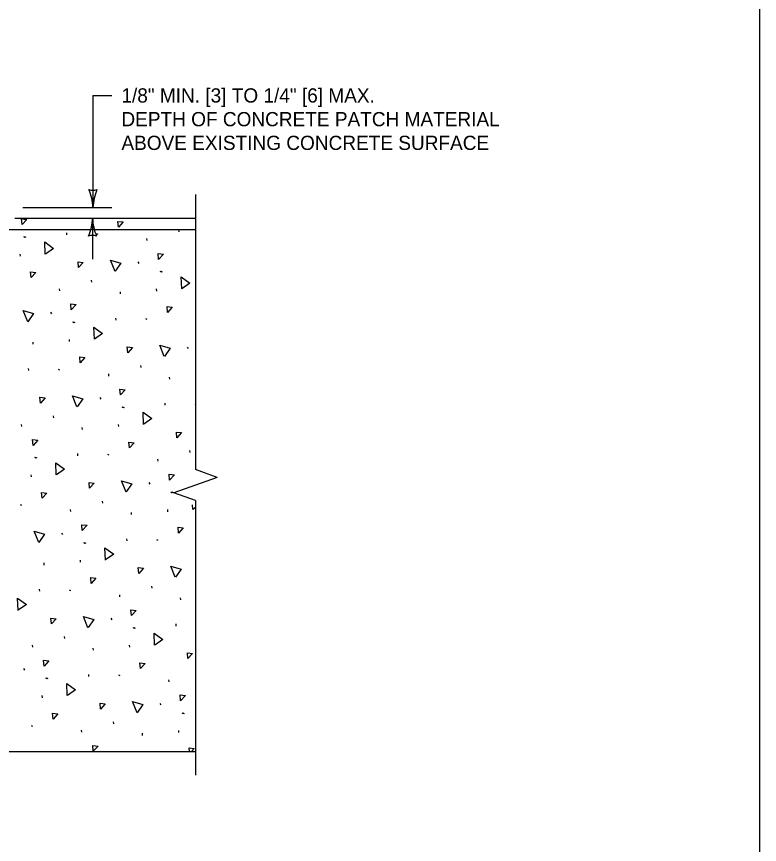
# Model space of a CAD drawing. Extents: x 49991.4 to 50021, y 49987.6 to 50011.4.
# Drawn here: x 50013.616 to 50016.75, y 49992.19 to 49995.683 of the extents above; entities that cross this region are included whole.
import ezdxf

# ---------------------------------------------------------------- set-up
doc = ezdxf.new("R2010")
doc.units = 0
for name, color, linetype in [('Level 1', 7, 'Continuous'), ('Level 2', 7, 'Continuous'), ('Level 3', 7, 'Continuous'), ('Level 4', 7, 'Continuous'), ('Level 6', 7, 'Continuous')]:
    doc.layers.add(name, color=color, linetype=linetype)

msp = doc.modelspace()

# ---------------------------------------------------------------- linework, layer by layer
at = {"layer": 'Level 1'}
msp.add_line((50013.6093, 49994.8328), (50014.3714, 49994.8328), dxfattribs=at)
msp.add_lwpolyline([(49999.3835, 49998.9992), (50016.7501, 49998.9992), (50016.7501, 49987.7988), (49999.3835, 49987.7988)], close=True, dxfattribs=at)
msp.add_lwpolyline([(50001.9803, 49992.5827), (50004.606, 49992.5827), (50014.3713, 49992.5827)], dxfattribs=at)
at = {"layer": 'Level 3'}
for p, q in [((50013.9385, 49995.3502), (50013.9385, 49994.8772)), ((50013.9385, 49995.3502), (50014.0185, 49995.3502)), ((50013.9367, 49994.8328), (50013.9367, 49994.6594))]:
    msp.add_line(p, q, dxfattribs=at)
msp.add_lwpolyline([(50013.6425, 49994.8772), (50013.8906, 49994.8772), (50014.0185, 49994.8772)], dxfattribs=at)
for centre, radius, start, end in [((50013.9385, 49995.0054), 0.0548, 252.1388, 287.8612), ((50013.7058, 49994.8657), 0.233, 2.8273, 22.0772), ((50014.1607, 49994.8681), 0.2223, 157.456, 177.6395), ((50013.7146, 49994.842), 0.2223, 337.456, 357.6395), ((50014.1694, 49994.8443), 0.233, 182.8273, 202.0772), ((50013.9367, 49994.7046), 0.0548, 72.1388, 107.8612)]:
    msp.add_arc(centre, radius, start, end, dxfattribs=at)
at = {"layer": 'Level 4'}
for p, q in [((50013.8287, 49994.7616), (50013.8278, 49994.7703)), ((50013.9533, 49994.7678), (50013.959, 49994.765)), ((50014.3022, 49994.7745), (50014.3013, 49994.7832)), ((50013.6448, 49994.755), (50013.6506, 49994.7522)), ((50013.6489, 49994.755), (50013.6547, 49994.7522)), ((50014.1671, 49994.7385), (50014.1662, 49994.7472)), ((50013.6324, 49994.6718), (50013.6315, 49994.6805)), ((50014.1278, 49994.648), (50014.1326, 49994.6416)), ((50014.2206, 49994.6084), (50014.2264, 49994.6056)), ((50014.2247, 49994.6085), (50014.2305, 49994.6056)), ((50013.9338, 49994.5618), (50013.9329, 49994.5705)), ((50013.7987, 49994.5258), (50013.7978, 49994.5345)), ((50014.2082, 49994.5252), (50014.2072, 49994.5339)), ((50014.0553, 49994.513), (50014.0544, 49994.5217)), ((50013.7594, 49994.4353), (50013.7642, 49994.4289)), ((50013.8522, 49994.3958), (50013.858, 49994.3929)), ((50013.8563, 49994.3958), (50013.8621, 49994.3929)), ((50014.0361, 49994.4023), (50014.0352, 49994.411)), ((50014.1607, 49994.4086), (50014.1664, 49994.4058)), ((50013.8398, 49994.3125), (50013.8389, 49994.3212)), ((50013.6869, 49994.3003), (50013.686, 49994.309)), ((50014.3352, 49994.2888), (50014.34, 49994.2823)), ((50014.1412, 49994.2025), (50014.1403, 49994.2112)), ((50013.6677, 49994.1896), (50013.6668, 49994.1983)), ((50013.7923, 49994.1959), (50013.798, 49994.1931)), ((50014.0061, 49994.1666), (50014.0052, 49994.1753)), ((50014.2627, 49994.1537), (50014.2618, 49994.1624)), ((50013.9668, 49994.0761), (50013.9716, 49994.0696)), ((50014.0597, 49994.0365), (50014.0654, 49994.0337)), ((50014.0637, 49994.0365), (50014.0695, 49994.0337)), ((50014.2435, 49994.0431), (50014.2426, 49994.0518)), ((50014.3681, 49994.0494), (50014.3713, 49994.0478)), ((50013.7728, 49993.9899), (50013.7719, 49993.9985)), ((50013.6377, 49993.9539), (50013.6368, 49993.9626)), ((50013.8943, 49993.941), (50013.8934, 49993.9497)), ((50014.0472, 49993.9533), (50014.0463, 49993.962)), ((50013.8751, 49993.8304), (50013.8742, 49993.8391)), ((50013.9997, 49993.8367), (50014.0054, 49993.8338)), ((50014.3486, 49993.8433), (50014.3477, 49993.852)), ((50013.6913, 49993.8238), (50013.697, 49993.821)), ((50013.6954, 49993.8238), (50013.7011, 49993.821)), ((50014.2135, 49993.8073), (50014.2126, 49993.816)), ((50013.6788, 49993.7406), (50013.6779, 49993.7493)), ((50014.1742, 49993.7169), (50014.179, 49993.7104)), ((50014.2671, 49993.6773), (50014.2728, 49993.6744)), ((50014.2712, 49993.6773), (50014.2769, 49993.6745)), ((50013.6313, 49993.624), (50013.637, 49993.6211)), ((50013.9802, 49993.6306), (50013.9793, 49993.6393)), ((50013.8451, 49993.5947), (50013.8442, 49993.6034)), ((50014.1017, 49993.5818), (50014.1008, 49993.5905)), ((50014.2546, 49993.5941), (50014.2537, 49993.6028)), ((50013.8058, 49993.5042), (50013.8106, 49993.4977)), ((50014.0825, 49993.4711), (50014.0816, 49993.4798)), ((50014.2071, 49993.4774), (50014.2128, 49993.4746)), ((50013.8987, 49993.4646), (50013.9044, 49993.4617)), ((50013.9028, 49993.4646), (50013.9085, 49993.4618)), ((50013.7333, 49993.3691), (50013.7324, 49993.3778)), ((50013.8862, 49993.3814), (50013.8853, 49993.3901)), ((50013.7142, 49993.2585), (50013.7132, 49993.2672)), ((50014.1876, 49993.2714), (50014.1867, 49993.2801)), ((50013.8387, 49993.2647), (50013.8444, 49993.2619)), ((50014.0525, 49993.2354), (50014.0516, 49993.2441)), ((50014.3091, 49993.2226), (50014.3082, 49993.2313)), ((50014.0132, 49993.1449), (50014.018, 49993.1385)), ((50014.1061, 49993.1053), (50014.1118, 49993.1025)), ((50014.1102, 49993.1054), (50014.1159, 49993.1025)), ((50014.29, 49993.1119), (50014.289, 49993.1206)), ((50013.8192, 49993.0587), (50013.8183, 49993.0674)), ((50013.6841, 49993.0227), (50013.6832, 49993.0314)), ((50014.0936, 49993.0221), (50014.0927, 49993.0308)), ((50013.9407, 49993.0099), (50013.9398, 49993.0186)), ((50013.6449, 49992.9322), (50013.6496, 49992.9258)), ((50013.7377, 49992.8927), (50013.7434, 49992.8898)), ((50013.7418, 49992.8927), (50013.7475, 49992.8898)), ((50013.9216, 49992.8992), (50013.9206, 49992.9079)), ((50014.0461, 49992.9055), (50014.0519, 49992.9027)), ((50014.2599, 49992.8762), (50014.259, 49992.8849)), ((50013.7252, 49992.8095), (50013.7243, 49992.8181)), ((50014.2206, 49992.7857), (50014.2254, 49992.7792)), ((50014.3135, 49992.7461), (50014.3192, 49992.7433)), ((50014.3176, 49992.7461), (50014.3233, 49992.7433)), ((50014.0267, 49992.6994), (50014.0257, 49992.7081)), ((50013.6777, 49992.6928), (50013.6835, 49992.69)), ((50013.8916, 49992.6635), (50013.8906, 49992.6722)), ((50014.301, 49992.6629), (50014.3001, 49992.6716)), ((50014.1481, 49992.6506), (50014.1472, 49992.6593))]:
    msp.add_line(p, q, dxfattribs=at)
for points in [[(50013.6394, 49994.8052), (50013.6376, 49994.8298), (50013.6596, 49994.8271), (50013.6394, 49994.8052)], [(50014.0455, 49994.7945), (50014.0437, 49994.819), (50014.0657, 49994.8164), (50014.0455, 49994.7945)], [(50013.7369, 49994.6809), (50013.735, 49994.7321), (50013.772, 49994.7052), (50013.7376, 49994.6813)], [(50014.2152, 49994.6586), (50014.2134, 49994.6832), (50014.2354, 49994.6805), (50014.2152, 49994.6586)], [(50013.8775, 49994.6241), (50013.8756, 49994.6487), (50013.8977, 49994.646), (50013.8775, 49994.6241)], [(50014.032, 49994.6078), (50014.0127, 49994.6553), (50014.0566, 49994.6428), (50014.0325, 49994.6085)], [(50013.6772, 49994.5818), (50013.6753, 49994.6063), (50013.6973, 49994.6037), (50013.6772, 49994.5818)], [(50014.3127, 49994.5343), (50014.3108, 49994.5855), (50014.3478, 49994.5587), (50014.3134, 49994.5347)], [(50013.8469, 49994.446), (50013.845, 49994.4705), (50013.867, 49994.4679), (50013.8469, 49994.446)], [(50014.253, 49994.4352), (50014.2511, 49994.4598), (50014.2731, 49994.4571), (50014.253, 49994.4352)], [(50013.6636, 49994.3952), (50013.6443, 49994.4426), (50013.6882, 49994.4301), (50013.6641, 49994.3958)], [(50013.9443, 49994.3216), (50013.9424, 49994.3728), (50013.9794, 49994.346), (50013.9451, 49994.3221)], [(50014.0849, 49994.2649), (50014.083, 49994.2895), (50014.1051, 49994.2868), (50014.0849, 49994.2649)], [(50014.2394, 49994.2486), (50014.2201, 49994.2961), (50014.264, 49994.2835), (50014.2399, 49994.2493)], [(50013.8846, 49994.2225), (50013.8827, 49994.2471), (50013.9047, 49994.2444), (50013.8846, 49994.2225)], [(50014.0543, 49994.0867), (50014.0524, 49994.1113), (50014.0744, 49994.1086), (50014.0543, 49994.0867)], [(50013.7165, 49994.0522), (50013.7146, 49994.0768), (50013.7367, 49994.0741), (50013.7165, 49994.0522)], [(50013.871, 49994.0359), (50013.8517, 49994.0834), (50013.8957, 49994.0708), (50013.8715, 49994.0366)], [(50014.1517, 49993.9624), (50014.1498, 49994.0136), (50014.1868, 49993.9868), (50014.1525, 49993.9628)], [(50014.2923, 49993.9057), (50014.2904, 49993.9302), (50014.3125, 49993.9276), (50014.2923, 49993.9057)], [(50013.6859, 49993.874), (50013.684, 49993.8986), (50013.706, 49993.8959), (50013.6859, 49993.874)], [(50014.092, 49993.8633), (50014.0901, 49993.8879), (50014.1121, 49993.8852), (50014.092, 49993.8633)], [(50013.7833, 49993.7497), (50013.7814, 49993.8009), (50013.8184, 49993.7741), (50013.7841, 49993.7501)], [(50014.0784, 49993.6767), (50014.0591, 49993.7241), (50014.1031, 49993.7116), (50014.0789, 49993.6774)], [(50014.2617, 49993.7275), (50014.2598, 49993.752), (50014.2818, 49993.7494), (50014.2617, 49993.7275)], [(50013.9239, 49993.693), (50013.922, 49993.7175), (50013.9441, 49993.7149), (50013.9239, 49993.693)], [(50013.7236, 49993.6506), (50013.7217, 49993.6752), (50013.7438, 49993.6725), (50013.7236, 49993.6506)], [(50014.3591, 49993.6031), (50014.3584, 49993.6232)], [(50014.3713, 49993.6116), (50014.3599, 49993.6036)], [(50013.71, 49993.464), (50013.6907, 49993.5115), (50013.7347, 49993.4989), (50013.7106, 49993.4647)], [(50013.8933, 49993.5148), (50013.8914, 49993.5393), (50013.9135, 49993.5367), (50013.8933, 49993.5148)], [(50014.2994, 49993.5041), (50014.2975, 49993.5286), (50014.3196, 49993.526), (50014.2994, 49993.5041)], [(50013.9907, 49993.3904), (50013.9888, 49993.4417), (50014.0259, 49993.4148), (50013.9915, 49993.3909)], [(50014.1313, 49993.3337), (50014.1295, 49993.3583), (50014.1515, 49993.3556), (50014.1313, 49993.3337)], [(50014.2858, 49993.3174), (50014.2665, 49993.3649), (50014.3105, 49993.3524), (50014.2864, 49993.3181)], [(50013.931, 49993.2914), (50013.9291, 49993.3159), (50013.9512, 49993.3133), (50013.931, 49993.2914)], [(50013.6223, 49993.1778), (50013.6204, 49993.229), (50013.6575, 49993.2021), (50013.6231, 49993.1782)], [(50014.1007, 49993.1556), (50014.0988, 49993.1801), (50014.1209, 49993.1775), (50014.1007, 49993.1556)], [(50013.7629, 49993.121), (50013.7611, 49993.1456), (50013.7831, 49993.1429), (50013.7629, 49993.121)], [(50013.9174, 49993.1047), (50013.8981, 49993.1522), (50013.9421, 49993.1397), (50013.918, 49993.1054)], [(50014.1981, 49993.0312), (50014.1962, 49993.0824), (50014.2333, 49993.0556), (50014.1989, 49993.0317)], [(50014.3387, 49992.9745), (50014.3369, 49992.999), (50014.3589, 49992.9964), (50014.3387, 49992.9745)], [(50013.7323, 49992.9429), (50013.7304, 49992.9674), (50013.7525, 49992.9648), (50013.7323, 49992.9429)], [(50014.1384, 49992.9321), (50014.1365, 49992.9567), (50014.1586, 49992.954), (50014.1384, 49992.9321)], [(50013.8297, 49992.8185), (50013.8279, 49992.8697), (50013.8649, 49992.8429), (50013.8305, 49992.819)], [(50014.3081, 49992.7963), (50014.3062, 49992.8209), (50014.3283, 49992.8182), (50014.3081, 49992.7963)], [(50013.9703, 49992.7618), (50013.9685, 49992.7864), (50013.9905, 49992.7837), (50013.9703, 49992.7618)], [(50014.1248, 49992.7455), (50014.1055, 49992.793), (50014.1495, 49992.7804), (50014.1254, 49992.7462)], [(50013.77, 49992.7194), (50013.7681, 49992.744), (50013.7902, 49992.7413), (50013.77, 49992.7194)], [(50013.9397, 49992.5836), (50013.9378, 49992.6082), (50013.9599, 49992.6055), (50013.9397, 49992.5836)], [(50014.3451, 49992.5827), (50014.3439, 49992.5974), (50014.366, 49992.5948), (50014.3548, 49992.5827)]]:
    msp.add_lwpolyline(points, dxfattribs=at)
at = {"layer": 'Level 6'}
for p, q in [((50014.3714, 49994.9328), (50014.3713, 49993.7715)), ((50014.3722, 49994.7828), (50008.1053, 49994.7828)), ((50014.4627, 49993.7391), (50014.3713, 49993.7715)), ((50014.4627, 49993.7391), (50014.3713, 49993.7067)), ((50014.3713, 49993.7067), (50014.2799, 49993.6743)), ((50014.3713, 49993.6419), (50014.2799, 49993.6743)), ((50014.3713, 49993.6419), (50014.3713, 49992.4827))]:
    msp.add_line(p, q, dxfattribs=at)

# ---------------------------------------------------------------- texts
at = {"layer": 'Level 2'}
for s, p in [('1/8" MIN. [3] TO 1/4" [6] MAX.', (50014.0585, 49995.3202)), ('DEPTH OF CONCRETE PATCH MATERIAL ', (50014.0585, 49995.2202)), ('ABOVE EXISTING CONCRETE SURFACE', (50014.0585, 49995.1202))]:
    msp.add_text(s, height=0.06, dxfattribs=at).set_placement(p)

doc.saveas('drawing.dxf')
